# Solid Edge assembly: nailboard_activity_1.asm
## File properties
Author: conerly
Template: ansi assembly.asm
Last saved by: jccrumbl
Revision: 89
Application: Solid Edge
Revision: 1
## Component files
Board.psm
Cable tie.par
14Pin.par
8PinRound.par
8PinSquare.par
3PinLongConnector.par
4PinConnector.par
5PinRoundConnector.par
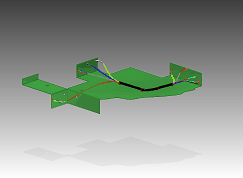
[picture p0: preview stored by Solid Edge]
